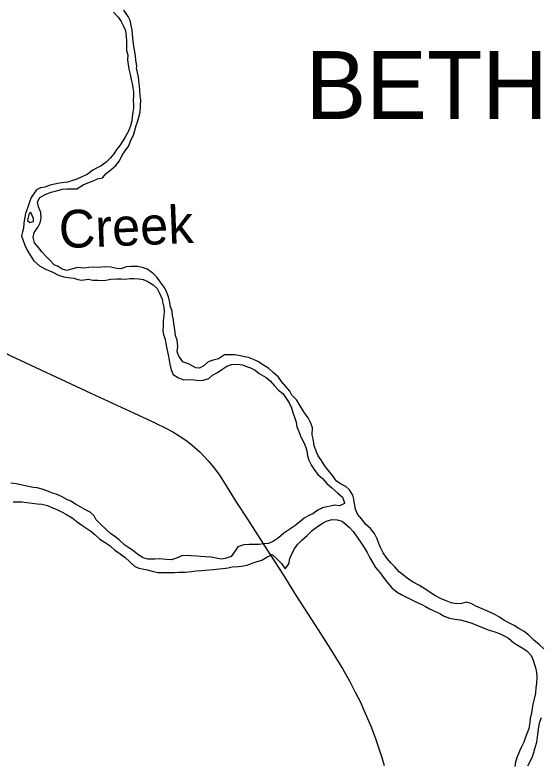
# Model space of a CAD drawing. Extents: x -6.3 to 34, y 0 to 22.
# Drawn here: x 3.325 to 4.228, y 14.392 to 15.677 of the extents above; entities that cross this region are included whole.
import ezdxf

# ---------------------------------------------------------------- set-up
doc = ezdxf.new("R2010")
doc.units = 0
for name, color, linetype in [('GM_X_Major_River', 7, 'Continuous'), ('GM_X_Major_River_Text', 7, 'Continuous'), ('GM_X_Township_Text', 7, 'Continuous'), ('GM_X_US_Route', 7, 'Continuous')]:
    doc.layers.add(name, color=color, linetype=linetype)

msp = doc.modelspace()

# ---------------------------------------------------------------- linework, layer by layer
at = {"layer": 'GM_X_Major_River'}
for points in [[(3.4948, 15.6814), (3.5026, 15.6731), (3.5078, 15.6653), (3.5112, 15.6583), (3.5154, 15.6497), (3.5162, 15.6404), (3.5167, 15.6318), (3.5167, 15.6237), (3.5172, 15.6157), (3.5191, 15.6079), (3.5186, 15.5996), (3.5196, 15.5913), (3.5209, 15.5832), (3.5235, 15.5744)], [(3.5265, 15.651), (3.5252, 15.6588), (3.5234, 15.6674), (3.5197, 15.6741), (3.5122, 15.6848)], [(3.6854, 15.0923), (3.6751, 15.0853), (3.666, 15.0832), (3.6572, 15.0803), (3.6505, 15.0743), (3.6427, 15.0696), (3.636, 15.0699), (3.6249, 15.0764), (3.6137, 15.0805), (3.6067, 15.0901), (3.6043, 15.0973), (3.6053, 15.1075), (3.6038, 15.1179), (3.6014, 15.1257), (3.6001, 15.1358), (3.5985, 15.1457), (3.598, 15.1524), (3.5959, 15.1602), (3.5954, 15.1677), (3.5928, 15.1747), (3.5912, 15.1825), (3.5894, 15.1919), (3.5854, 15.2023), (3.5815, 15.209), (3.5751, 15.2181), (3.5696, 15.2256), (3.5621, 15.2326), (3.5527, 15.2394), (3.5447, 15.2425), (3.5356, 15.244), (3.5253, 15.244), (3.5162, 15.2437), (3.5069, 15.2401), (3.5001, 15.2406), (3.49, 15.2434), (3.4799, 15.2439), (3.4695, 15.2428), (3.461, 15.2434), (3.4522, 15.2428), (3.4434, 15.2415), (3.433, 15.2423), (3.4224, 15.2394), (3.4141, 15.2376), (3.4063, 15.2399), (3.3993, 15.244), (3.3926, 15.2471), (3.3853, 15.2549), (3.3786, 15.2614), (3.3715, 15.2697), (3.3653, 15.2769), (3.3586, 15.2852), (3.3562, 15.2943), (3.3583, 15.3029), (3.365, 15.3123), (3.3683, 15.3193), (3.3701, 15.3276), (3.3696, 15.337), (3.3657, 15.3468), (3.3639, 15.3554), (3.368, 15.3627), (3.3768, 15.3679), (3.3871, 15.3718), (3.3941, 15.3736), (3.4068, 15.377), (3.4141, 15.3776), (3.4312, 15.3776), (3.4426, 15.3844), (3.4506, 15.388), (3.4597, 15.3914), (3.4669, 15.3951), (3.4757, 15.3969), (3.4822, 15.4044), (3.4902, 15.4107), (3.4985, 15.418), (3.5047, 15.426), (3.5093, 15.4354), (3.5147, 15.4429), (3.5207, 15.4515), (3.5246, 15.4614), (3.5287, 15.47), (3.531, 15.4783), (3.5336, 15.4864), (3.5359, 15.4929), (3.5379, 15.5007), (3.5403, 15.5095), (3.541, 15.5196), (3.5415, 15.5308), (3.5407, 15.5375), (3.5399, 15.5466), (3.5391, 15.5542), (3.5381, 15.5633), (3.5373, 15.5703), (3.5341, 15.5851), (3.5346, 15.5885), (3.533, 15.5997), (3.5325, 15.6059), (3.5309, 15.6165), (3.5298, 15.6225), (3.5285, 15.6324), (3.5271, 15.6428), (3.5265, 15.651)], [(3.5235, 15.5744), (3.5251, 15.5658), (3.5264, 15.5591), (3.528, 15.5516), (3.5288, 15.5448), (3.5291, 15.537), (3.5283, 15.5295), (3.5288, 15.523), (3.5288, 15.5162), (3.5281, 15.5095), (3.5268, 15.5014), (3.526, 15.4947), (3.5237, 15.4863), (3.5201, 15.477), (3.5155, 15.4689), (3.5116, 15.4619), (3.5054, 15.4525), (3.5005, 15.446), (3.4951, 15.4377), (3.4896, 15.4312), (3.4811, 15.4229), (3.4733, 15.4174), (3.4664, 15.4138), (3.4591, 15.4096), (3.449, 15.4023), (3.44, 15.3984), (3.4312, 15.3942), (3.4226, 15.3916), (3.4154, 15.3893), (3.4054, 15.388), (3.3981, 15.3869), (3.3857, 15.384), (3.3767, 15.3808), (3.3692, 15.3795), (3.3622, 15.3759), (3.3529, 15.3626), (3.3498, 15.3548), (3.3468, 15.3445), (3.3432, 15.3356), (3.3414, 15.3263), (3.3401, 15.319), (3.3396, 15.3104), (3.3383, 15.3037), (3.3363, 15.2972), (3.3389, 15.2891), (3.3422, 15.2808), (3.3461, 15.2722), (3.3513, 15.2637), (3.3578, 15.2541), (3.3672, 15.2453), (3.3765, 15.2403), (3.39, 15.2346), (3.3999, 15.2295), (3.4092, 15.2264), (3.4159, 15.2251), (3.4261, 15.2243), (3.4331, 15.222), (3.4403, 15.2205), (3.4507, 15.2225), (3.4592, 15.2207), (3.4678, 15.2205), (3.4748, 15.2203), (3.4815, 15.2208), (3.4901, 15.2226), (3.5004, 15.2232), (3.5077, 15.2232), (3.5149, 15.2227), (3.523, 15.2237), (3.5297, 15.2237), (3.5382, 15.223), (3.5455, 15.2222), (3.5535, 15.2186), (3.5626, 15.2129), (3.5696, 15.2067), (3.5738, 15.1984), (3.578, 15.188), (3.5793, 15.1815), (3.5814, 15.1745), (3.5816, 15.1669), (3.5809, 15.1599), (3.5801, 15.1506), (3.5801, 15.1417), (3.5796, 15.1337), (3.5807, 15.1272), (3.5835, 15.1189), (3.5846, 15.1121), (3.5862, 15.103), (3.5888, 15.0927), (3.5904, 15.0833), (3.5914, 15.0766), (3.594, 15.0669), (3.5971, 15.0586), (3.6062, 15.0527), (3.6158, 15.0493), (3.6257, 15.0499), (3.6332, 15.0496), (3.6412, 15.0483), (3.6487, 15.0489), (3.6583, 15.052), (3.665, 15.0575), (3.6733, 15.0619)], [(3.3523, 15.3371), (3.3494, 15.3358), (3.3469, 15.3231), (3.3507, 15.3198)], [(3.3507, 15.3198), (3.357, 15.3218), (3.3567, 15.3268), (3.3523, 15.3371)], [(3.9074, 14.8465), (3.9061, 14.8514), (3.9007, 14.8605), (3.8942, 14.8662), (3.8862, 14.87), (3.8781, 14.8755), (3.8714, 14.8848), (3.8639, 14.8939), (3.8577, 14.902), (3.8525, 14.9108), (3.8467, 14.9188), (3.8441, 14.924), (3.8397, 14.9362), (3.838, 14.9481), (3.8365, 14.9551), (3.8367, 14.9668), (3.8339, 14.9752), (3.8292, 14.9842), (3.8217, 14.9944), (3.8141, 15.0076), (3.8097, 15.0143), (3.8014, 15.0232), (3.7977, 15.0299), (3.791, 15.0379), (3.7835, 15.0465), (3.7783, 15.0538), (3.7692, 15.0621), (3.7616, 15.0691), (3.7528, 15.0745), (3.7427, 15.0812), (3.7354, 15.0843), (3.7266, 15.0877), (3.7199, 15.0887), (3.7129, 15.0905), (3.7033, 15.0926), (3.6945, 15.0923), (3.6854, 15.0923)], [(3.6733, 15.0619), (3.6808, 15.0674), (3.6893, 15.0731), (3.6976, 15.076), (3.708, 15.0765), (3.7166, 15.075), (3.7236, 15.0721), (3.7303, 15.0698), (3.7381, 15.0662), (3.7453, 15.0605), (3.7573, 15.0535), (3.7643, 15.0478), (3.7718, 15.0392), (3.7786, 15.0314), (3.7856, 15.0257), (3.7913, 15.0187), (3.797, 15.0099), (3.8009, 15.0013), (3.803, 14.9933), (3.8059, 14.9855), (3.8087, 14.9767), (3.81, 14.9686), (3.8134, 14.9606), (3.8166, 14.9517), (3.8215, 14.9429), (3.8246, 14.9346), (3.827, 14.9273), (3.8283, 14.919), (3.8306, 14.9112), (3.8353, 14.9022), (3.8397, 14.8954), (3.8462, 14.8866), (3.8543, 14.8799), (3.8615, 14.8713), (3.8701, 14.864), (3.8797, 14.855), (3.8885, 14.8477), (3.8917, 14.8381)], [(3.8917, 14.8381), (3.8917, 14.8368), (3.8836, 14.8331), (3.8748, 14.8339), (3.8681, 14.8321), (3.8614, 14.831), (3.8541, 14.8292), (3.8461, 14.8253), (3.8375, 14.8193), (3.8308, 14.8162), (3.8225, 14.8117), (3.815, 14.8052), (3.8065, 14.7982), (3.7964, 14.7917), (3.7876, 14.7857), (3.7785, 14.7779), (3.77, 14.7719), (3.7612, 14.7682), (3.7527, 14.7674), (3.7454, 14.7661), (3.7369, 14.7664), (3.728, 14.7666), (3.7187, 14.7658), (3.7086, 14.7622), (3.7029, 14.7536), (3.6967, 14.7455), (3.6869, 14.7421), (3.6799, 14.7413), (3.6713, 14.7431), (3.6623, 14.7447), (3.6529, 14.7454), (3.6444, 14.746), (3.6377, 14.7462), (3.6283, 14.747), (3.6216, 14.7475), (3.6123, 14.7469), (3.6029, 14.7428), (3.5944, 14.7401), (3.5851, 14.7404), (3.5744, 14.7417), (3.5654, 14.7414), (3.5537, 14.7409), (3.5457, 14.7434), (3.5366, 14.7494), (3.5275, 14.7569), (3.5208, 14.7608), (3.514, 14.7652), (3.5042, 14.7745), (3.4966, 14.7802), (3.4896, 14.7854), (3.4813, 14.7929), (3.472, 14.8012), (3.4647, 14.809), (3.4611, 14.8158), (3.4546, 14.8217), (3.4463, 14.8261), (3.4385, 14.8308), (3.4292, 14.836), (3.4214, 14.8406), (3.4141, 14.8435), (3.405, 14.8487), (3.3957, 14.8531), (3.3879, 14.8554), (3.3796, 14.8585), (3.3721, 14.8613), (3.3635, 14.8636), (3.3565, 14.8644), (3.3483, 14.866), (3.3273, 14.8706), (3.3182, 14.8721)], [(4.2347, 14.5872), (4.2266, 14.5942), (4.2176, 14.602), (4.2093, 14.6103), (4.2009, 14.6168), (4.1921, 14.6217), (4.1836, 14.6269), (4.1745, 14.6318), (4.1662, 14.6365), (4.1584, 14.6417), (4.1504, 14.6458), (4.1418, 14.6499), (4.1327, 14.6541), (4.1247, 14.6577), (4.1177, 14.6606), (4.1099, 14.665), (4.1016, 14.667), (4.0933, 14.6649), (4.0843, 14.6646), (4.0754, 14.6662), (4.0671, 14.6693), (4.057, 14.6737), (4.0482, 14.6781), (4.0394, 14.6838), (4.0301, 14.69), (4.0207, 14.6957), (4.0103, 14.7019), (4.0023, 14.7068), (3.9942, 14.7133), (3.9859, 14.7195), (3.9784, 14.7278), (3.9717, 14.7346), (3.9649, 14.7429), (3.9587, 14.7522), (3.954, 14.7611), (3.9509, 14.7681), (3.948, 14.7764), (3.9433, 14.7852), (3.9366, 14.7938), (3.9283, 14.8015), (3.9218, 14.8101), (3.9145, 14.8184), (3.9106, 14.8272), (3.9074, 14.8465)], [(3.3219, 14.8397), (3.3286, 14.8397), (3.3366, 14.8397), (3.3452, 14.8384), (3.3548, 14.8377), (3.3631, 14.8364), (3.3714, 14.8356), (3.381, 14.8333), (3.3887, 14.8302), (3.3957, 14.8273), (3.4051, 14.8224), (3.4139, 14.8178), (3.4232, 14.8123), (3.4318, 14.8051), (3.4401, 14.7994), (3.4469, 14.795), (3.4557, 14.7893), (3.4629, 14.783), (3.471, 14.7758), (3.4801, 14.7696), (3.4891, 14.7639), (3.4969, 14.7566), (3.5058, 14.7501), (3.5146, 14.7439), (3.5229, 14.7364), (3.5309, 14.7291), (3.5382, 14.7255), (3.5468, 14.7241), (3.5527, 14.7228), (3.5636, 14.72), (3.5711, 14.7185), (3.576, 14.7182), (3.5833, 14.7185), (3.5905, 14.7185), (3.5994, 14.7183), (3.6076, 14.7186), (3.6177, 14.7186), (3.6289, 14.72), (3.6366, 14.7213), (3.6465, 14.7219), (3.6524, 14.7222), (3.6597, 14.723), (3.6664, 14.7233), (3.6762, 14.7243), (3.6827, 14.7251), (3.692, 14.7265), (3.6985, 14.7278), (3.7096, 14.7286), (3.715, 14.7294), (3.7247, 14.731), (3.733, 14.7342), (3.74, 14.7363), (3.7496, 14.7396), (3.7584, 14.7446), (3.7677, 14.749), (3.7758, 14.7418), (3.7836, 14.7337)], [(3.7836, 14.7337), (3.7898, 14.7246), (3.7963, 14.7332), (3.798, 14.7423), (3.8014, 14.7506), (3.806, 14.7592), (3.811, 14.7663), (3.8185, 14.7738), (3.828, 14.7819), (3.8363, 14.7905), (3.8456, 14.7972), (3.8554, 14.8037), (3.8624, 14.8069), (3.8707, 14.8095), (3.8793, 14.809), (3.8879, 14.8067)], [(3.8879, 14.8067), (3.9008, 14.7955), (3.907, 14.7885), (3.9135, 14.7792), (3.9198, 14.7698), (3.9258, 14.7613), (3.931, 14.7524), (3.9356, 14.7434), (3.9414, 14.7338), (3.9455, 14.727), (3.9533, 14.7174), (3.9603, 14.7078), (3.9671, 14.6995), (3.9736, 14.6917), (3.9824, 14.6847), (3.9896, 14.6803), (3.9987, 14.6757), (4.0068, 14.672), (4.0158, 14.6674), (4.0247, 14.6632), (4.0314, 14.6599), (4.0382, 14.656), (4.0454, 14.6524), (4.0558, 14.6475), (4.0633, 14.6433), (4.0724, 14.6399), (4.082, 14.6381), (4.091, 14.6366), (4.1017, 14.6343), (4.1107, 14.6312), (4.1206, 14.6273), (4.1305, 14.6232), (4.1408, 14.6193), (4.1489, 14.617), (4.1587, 14.6133), (4.1657, 14.61), (4.174, 14.6051), (4.1834, 14.5973), (4.1904, 14.5926), (4.1974, 14.5887), (4.2057, 14.5836), (4.2132, 14.5758), (4.2166, 14.5675), (4.2187, 14.5599), (4.221, 14.5527), (4.2223, 14.5459), (4.2229, 14.5381), (4.2224, 14.5283), (4.2213, 14.5199), (4.2203, 14.5111), (4.2183, 14.5012), (4.2165, 14.4942), (4.2149, 14.4849), (4.2134, 14.4771), (4.2116, 14.4672), (4.2108, 14.4604), (4.2088, 14.45), (4.207, 14.4435), (4.2034, 14.4352), (4.2003, 14.4266), (4.1956, 14.4175), (4.1928, 14.411), (4.1892, 14.4014), (4.1861, 14.3926), (4.1851, 14.385)], [(4.2076, 14.3861), (4.2122, 14.3957), (4.2153, 14.4022), (4.2174, 14.4087), (4.22, 14.4173), (4.2228, 14.4264), (4.2238, 14.4358), (4.2251, 14.4443), (4.2261, 14.4527), (4.2282, 14.4615), (4.2308, 14.4688)]]:
    msp.add_lwpolyline(points, dxfattribs=at)
at = {"layer": 'GM_X_US_Route'}
for points in [[(3.1036, 15.1948), (3.1171, 15.197), (3.1253, 15.1973), (3.1331, 15.1965), (3.1403, 15.1948), (3.1485, 15.1924), (3.1573, 15.1887), (3.1678, 15.1829), (3.1865, 15.1718), (3.1974, 15.165), (3.22, 15.1508), (3.2407, 15.1376), (3.2656, 15.1216), (3.2904, 15.1061), (3.3057, 15.0971), (3.3182, 15.0905), (3.4556, 15.0265), (3.5227, 14.9956), (3.5663, 14.9755)], [(3.5663, 14.9755), (3.5669, 14.9752), (3.5834, 14.9672), (3.5966, 14.9602), (3.6076, 14.9533), (3.6189, 14.9457), (3.6298, 14.9371), (3.6436, 14.9249), (3.6575, 14.9103), (3.6671, 14.8989), (3.6769, 14.8853), (3.6869, 14.8702), (3.7063, 14.8387), (3.7249, 14.8097), (3.7583, 14.7578), (3.7858, 14.7151), (3.8089, 14.6783), (3.8468, 14.6195), (3.8676, 14.5862), (3.8888, 14.5522), (3.9012, 14.5306), (3.9105, 14.5123), (3.9193, 14.4951), (3.9235, 14.4856), (3.9376, 14.4528), (3.9451, 14.4329), (3.9511, 14.4155), (3.956, 14.4005), (3.9604, 14.3864)]]:
    msp.add_lwpolyline(points, dxfattribs=at)

# ---------------------------------------------------------------- texts
at = {"layer": 'GM_X_Major_River_Text'}
msp.add_text('Creek', height=0.0649, rotation=2.3117, dxfattribs=at).set_placement((3.4018, 15.2755))
at = {"layer": 'GM_X_Township_Text'}
msp.add_text('BETHLEHEM', height=0.11682, rotation=0, dxfattribs=at).set_placement((3.8252, 15.4979))

doc.saveas('drawing.dxf')
